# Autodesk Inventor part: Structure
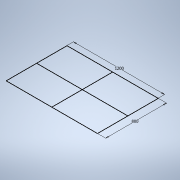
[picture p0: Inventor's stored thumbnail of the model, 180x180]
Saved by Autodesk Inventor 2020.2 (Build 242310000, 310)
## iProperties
Created: 2020-01
Part Number: Structure
Material: Generic
Document SubType Name: Modeling
Designer: thira
Density: 1 g/cm^3
Appearance: Default
Author: thira
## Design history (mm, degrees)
sketch "Sketch1"
  geometry: L1 (0, 0)-(-1200, 0); L2 (-1200, 0)-(-1200, -800); L3 (-1200, -800)-(0, -800); L4 (0, -800)-(0, 0); L5 (0, -400)-(-1200, -400); L6 (-600, -800)-(-600, 0)
  constraints: 12 end point, 4 midpoint, 2 parallel, 1 horizontal, 1 perpendicular
  dimensions: "d0" = 1200 dimension on L1.start L2.end L1.end L3.end L1 L2 L3 L4 L5.start L5.end L5 L6.start L6.end L6; "d0" = 1200 distance of L3.end L2.end; "d1" = 800 distance of L2.end L1.end
